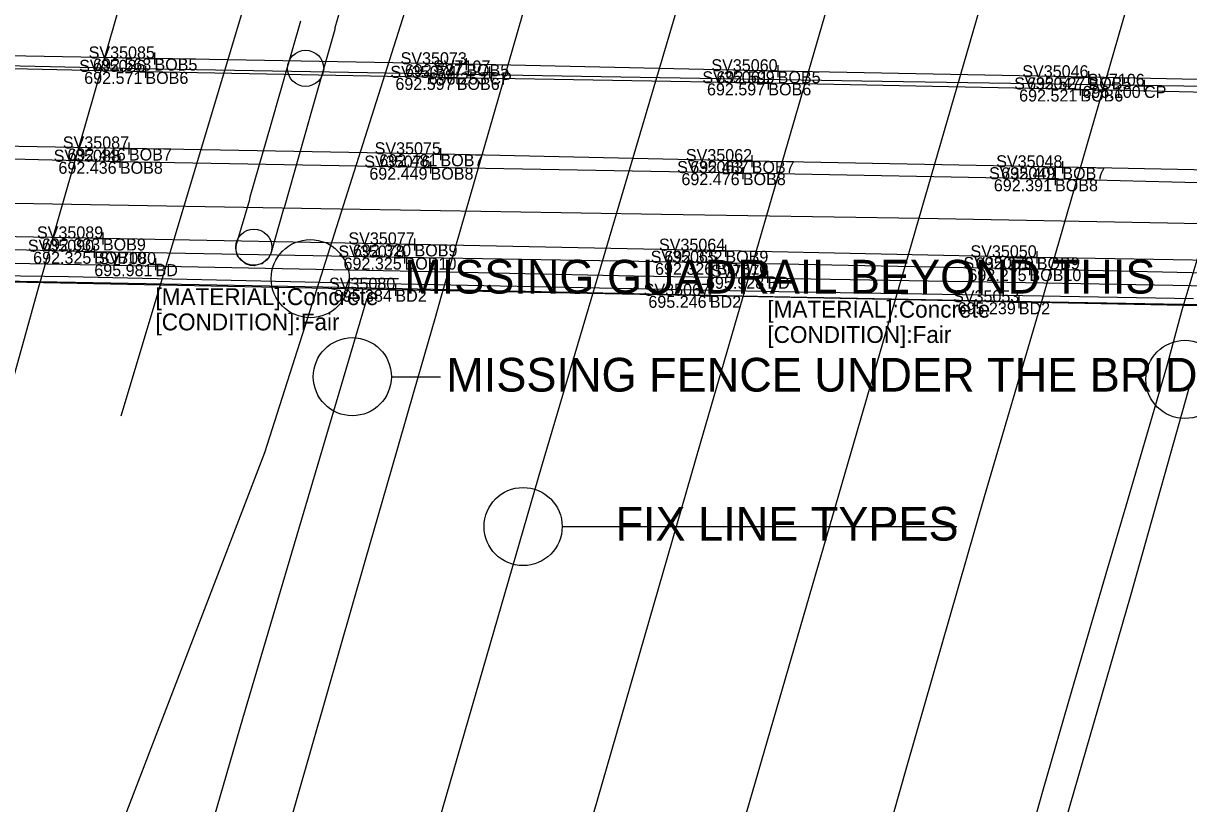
# Model space of a CAD drawing. Extents: x 1659932 to 1663108, y 619867 to 620611.
# Drawn here: x 1661352.9 to 1661449.7, y 620170.2 to 620235.1 of the extents above; entities that cross this region are included whole.
import ezdxf

# ---------------------------------------------------------------- set-up
doc = ezdxf.new("R2010")
doc.units = 0
for name, color, linetype in [('BR_X_Rail_Object', 7, 'Continuous'), ('BR_X_SV_Bottom_of_Beam', 7, 'Continuous'), ('BR_X_SV_Bottom_of_Beam_Text', 7, 'Continuous'), ('BR_X_SV_Deck_Top', 7, 'Continuous'), ('BR_X_SV_Deck_Top_Text', 7, 'Continuous'), ('BR_X_SV_Pier_Cap_Top', 7, 'Continuous'), ('PM_X_CL_Double_Solid', 7, 'Continuous'), ('PM_X_Edge_Line', 7, 'Continuous'), ('PM_X_Lane_Line', 7, 'Continuous'), ('PV_X_EOP', 7, 'Continuous'), ('RD_X_Fence', 7, 'Continuous'), ('RD_X_GR_Lt', 7, 'Continuous'), ('RD_X_GR_Rt', 7, 'Continuous'), ('SC_Scratch6', 7, 'Continuous'), ('SV_X_Break_Lines', 7, 'Continuous'), ('SV_X_Shot_Marker', 7, 'Continuous'), ('SV_X_Text', 7, 'Continuous'), ('SV_X_Text_Comment', 7, 'Continuous'), ('SV_X_Text_Elevation', 7, 'Continuous'), ('SV_X_Text_Name', 7, 'Continuous')]:
    doc.layers.add(name, color=color, linetype=linetype)

msp = doc.modelspace()

# ---------------------------------------------------------------- linework, layer by layer
at = {"layer": 'BR_X_Rail_Object'}
for points in [[(1661277.086, 620215.156), (1661299.829, 620214.642), (1661320.762, 620214.229), (1661340.158, 620213.856), (1661357.268, 620213.542), (1661379.28, 620213.128), (1661397.221, 620212.742), (1661415.211, 620212.369), (1661433.513, 620212.015), (1661450.818, 620211.691)], [(1661450.154, 620212.164), (1661434.35, 620212.457), (1661415.687, 620212.757), (1661398.089, 620213.11), (1661378.816, 620213.501), (1661356.678, 620213.984), (1661338.689, 620214.253), (1661319.507, 620214.681), (1661300.196, 620215.004), (1661277.496, 620215.529)]]:
    msp.add_lwpolyline(points, dxfattribs=at)
at = {"layer": 'BR_X_SV_Bottom_of_Beam'}
for points in [[(1661519.081, 620228.953), (1661493.234, 620229.438), (1661467.368, 620230.031), (1661441.422, 620230.57), (1661415.6, 620231.071), (1661389.731, 620231.651), (1661363.823, 620232.132), (1661337.817, 620232.613), (1661311.988, 620233.076), (1661286.183, 620233.721), (1661260.328, 620234.129), (1661234.382, 620234.656)], [(1661518.51, 620227.977), (1661492.527, 620228.475), (1661466.56, 620228.954), (1661440.742, 620229.56), (1661414.823, 620230.069), (1661388.938, 620230.522), (1661363.07, 620231.021), (1661337.298, 620231.612), (1661311.527, 620232.162), (1661285.446, 620232.587), (1661259.588, 620233.138), (1661233.669, 620233.674)], [(1661516.938, 620221.488), (1661491.079, 620222.019), (1661465.187, 620222.58), (1661439.251, 620223.092), (1661413.441, 620223.61), (1661387.584, 620224.174), (1661361.703, 620224.657), (1661335.742, 620225.126), (1661309.876, 620225.693), (1661284.015, 620226.238), (1661258.155, 620226.696), (1661232.1, 620227.235)], [(1661516.255, 620220.542), (1661490.624, 620220.907), (1661464.53, 620221.454), (1661438.64, 620222.101), (1661412.707, 620222.613), (1661386.76, 620223.066), (1661360.949, 620223.557), (1661335.05, 620224.176), (1661309.206, 620224.717), (1661283.267, 620225.126), (1661257.537, 620225.694), (1661231.605, 620226.262)], [(1661514.756, 620214.059), (1661488.914, 620214.555), (1661463.017, 620215.148), (1661437.126, 620215.616), (1661411.256, 620216.167), (1661385.428, 620216.691), (1661359.541, 620217.184), (1661333.602, 620217.682), (1661307.754, 620218.183), (1661281.891, 620218.773), (1661255.858, 620219.275), (1661229.67, 620219.799)], [(1661514.073, 620213.08), (1661488.21, 620213.597), (1661462.263, 620214.044), (1661436.515, 620214.643), (1661410.516, 620215.165), (1661384.602, 620215.601), (1661358.815, 620216.084), (1661332.968, 620216.701), (1661307.113, 620217.251), (1661281.101, 620217.691), (1661255.319, 620218.266), (1661229.464, 620218.851)]]:
    msp.add_lwpolyline(points, dxfattribs=at)
at = {"layer": 'BR_X_SV_Deck_Top'}
msp.add_lwpolyline([(1661513.529, 620210.295), (1661487.664, 620211.099), (1661461.66, 620211.354), (1661435.632, 620211.885), (1661409.962, 620212.424), (1661383.838, 620212.928), (1661332.298, 620213.947), (1661306.248, 620214.439), (1661280.429, 620214.969), (1661254.732, 620215.771)], dxfattribs=at)
at = {"layer": 'BR_X_SV_Pier_Cap_Top'}
msp.add_lwpolyline([(1661380.938, 620242.011), (1661378.818, 620234.677), (1661378.805, 620234.545), (1661376.714, 620227.175), (1661376.664, 620227.078), (1661374.594, 620219.738), (1661374.533, 620219.633), (1661373.508, 620216.005), (1661373.304, 620215.554), (1661373.028, 620215.339), (1661372.782, 620215.083), (1661372.463, 620215.014), (1661372.113, 620214.903), (1661371.815, 620214.94), (1661371.397, 620215.075), (1661371.042, 620215.405), (1661370.729, 620215.71), (1661370.615, 620216.195), (1661370.607, 620216.504), (1661370.678, 620216.801), (1661371.744, 620220.429), (1661371.783, 620220.63), (1661373.87, 620227.928), (1661373.92, 620228.026), (1661375.992, 620235.256)], dxfattribs=at)
at = {"layer": 'PM_X_CL_Double_Solid'}
msp.add_lwpolyline([(1661546.991, 620228.003), (1661534.02, 620228.314), (1661515.703, 620228.672), (1661490.63, 620229.199), (1661465.719, 620229.574), (1661443.889, 620229.917), (1661424.27, 620230.219), (1661405.796, 620230.53), (1661384.669, 620230.881), (1661362.569, 620231.272), (1661341.508, 620231.739), (1661317.992, 620232.235), (1661293.686, 620232.891), (1661270.168, 620233.351), (1661246.396, 620233.829), (1661221.676, 620234.257), (1661205.714, 620234.618)], dxfattribs=at)
at = {"layer": 'PM_X_Edge_Line'}
for p, q in [((1661400.11, 620212.126), (1661411.11, 620249.281)), ((1661448.095, 620248.463), (1661437.387, 620211.448))]:
    msp.add_line(p, q, dxfattribs=at)
for points in [[(1661202.201, 620223.591), (1661213.111, 620223.268), (1661228.394, 620222.766), (1661259.553, 620221.998), (1661275.152, 620221.639), (1661292.516, 620221.273), (1661314.563, 620220.783), (1661337.968, 620220.356), (1661364.828, 620219.904), (1661379.245, 620219.635), (1661405.952, 620219.205), (1661427.476, 620218.875), (1661447.989, 620218.475), (1661471.403, 620218.024), (1661496.022, 620217.585), (1661519.238, 620217.199), (1661540.284, 620216.766), (1661543.975, 620216.723)], [(1661306.71, 619886.778), (1661316.268, 619920.92), (1661327.099, 619959.195), (1661339.626, 620003.423), (1661350.518, 620041.544), (1661361.573, 620079.456), (1661372.715, 620118.483), (1661384.459, 620158.407), (1661395.985, 620198.192), (1661400.11, 620212.126)], [(1661437.387, 620211.448), (1661432.744, 620195.727), (1661426.311, 620173.263), (1661420.721, 620153.567), (1661415.987, 620137.071), (1661411.465, 620121.721), (1661406.956, 620105.485), (1661401.842, 620087.622), (1661396.469, 620069.251), (1661391.034, 620050.3), (1661384.749, 620028.544), (1661378.434, 620007.007), (1661371.358, 619982.439), (1661363.477, 619954.98), (1661355.622, 619926.778), (1661348.804, 619903.188), (1661342.453, 619880.74)]]:
    msp.add_lwpolyline(points, dxfattribs=at)
at = {"layer": 'PM_X_Lane_Line'}
for p, q in [((1661409.184, 620200.168), (1661424.053, 620251.255)), ((1661436.528, 620250.631), (1661421.891, 620200.155))]:
    msp.add_line(p, q, dxfattribs=at)
for points in [[(1661320.334, 619891.193), (1661330.953, 619928.285), (1661342.834, 619969.596), (1661354.182, 620009.137), (1661364.936, 620046.768), (1661375.793, 620084.601), (1661387.194, 620123.919), (1661398.334, 620162.593), (1661409.184, 620200.168)], [(1661421.891, 620200.155), (1661410.557, 620161.046), (1661398.591, 620119.699), (1661388.314, 620083.982), (1661377.532, 620046.533), (1661365.852, 620005.722), (1661355.434, 619969.431), (1661344.025, 619929.62), (1661333.166, 619890.94)]]:
    msp.add_lwpolyline(points, dxfattribs=at)
at = {"layer": 'PV_X_EOP'}
for p, q in [((1661364.882, 620250.347), (1661354.068, 620212.758)), ((1661387.682, 620212.413), (1661398.34, 620249.454)), ((1661460.209, 620248.191), (1661449.175, 620211.228))]:
    msp.add_line(p, q, dxfattribs=at)
for points in [[(1661354.068, 620212.758), (1661351.456, 620203.266), (1661348.504, 620193.032), (1661343.865, 620176.722), (1661338.343, 620157.33), (1661329.496, 620126.951), (1661323.428, 620105.423), (1661317.627, 620085.661), (1661309.752, 620058.017), (1661302.017, 620030.687), (1661292.653, 619998.313), (1661288.526, 619983.086), (1661284.456, 619969.782), (1661279.629, 619952.971), (1661274.634, 619935.67), (1661263.801, 619897.546), (1661258.099, 619878.266)], [(1661288.662, 619867.177), (1661292.293, 619880.139), (1661297.982, 619900.237), (1661302.563, 619916.13), (1661307.386, 619933.253), (1661312.432, 619950.929), (1661316.287, 619964.745), (1661318.419, 619972.097), (1661332.213, 620019.935), (1661339.457, 620045.301), (1661345.341, 620066.158), (1661348.977, 620078.854), (1661352.806, 620092.257), (1661356.714, 620105.692), (1661360.704, 620119.003), (1661364.644, 620132.564), (1661371.894, 620157.469), (1661378.106, 620179.182), (1661381.364, 620190.492), (1661383.517, 620197.974), (1661385.373, 620204.43), (1661387.148, 620210.533), (1661387.682, 620212.413)], [(1661449.175, 620211.228), (1661447.901, 620206.5), (1661444.533, 620194.957), (1661443.009, 620189.805), (1661440.022, 620179.591), (1661437.667, 620171.441), (1661433.645, 620157.193), (1661427.975, 620137.724), (1661425.116, 620127.734), (1661422.329, 620118.155), (1661418.054, 620103.53), (1661414.465, 620091.14), (1661411.007, 620079.046), (1661408.706, 620071.095), (1661405.629, 620060.218), (1661402.596, 620050.021), (1661399.373, 620038.801), (1661396.017, 620026.958)]]:
    msp.add_lwpolyline(points, dxfattribs=at)
at = {"layer": 'RD_X_Fence'}
msp.add_lwpolyline([(1661324.855, 620042.073), (1661333.159, 620048.256), (1661338.09, 620064.232), (1661346.292, 620092.377), (1661351.34, 620109.776), (1661359.715, 620137.883), (1661371.17, 620177.306), (1661381.505, 620212.212)], dxfattribs=at)
at = {"layer": 'RD_X_GR_Lt'}
for p, q in [((1661376.955, 620211.812), (1661392.542, 620260.947)), ((1661377.013, 620255.729), (1661361.042, 620202.435))]:
    msp.add_line(p, q, dxfattribs=at)
msp.add_lwpolyline([(1661337.672, 620097.681), (1661344.162, 620121.221), (1661348.962, 620136.596), (1661353.107, 620148.16), (1661357.657, 620159.513), (1661368.944, 620188.88), (1661372.986, 620199.407), (1661376.955, 620211.812)], dxfattribs=at)
at = {"layer": 'RD_X_GR_Rt'}
msp.add_lwpolyline([(1661385.522, 619982.005), (1661394.011, 620012.081), (1661399.542, 620030.546), (1661408.076, 620060.366), (1661416.511, 620089.472), (1661427.104, 620125.794), (1661434.884, 620152.781), (1661444.901, 620187.452), (1661449.997, 620205.546)], dxfattribs=at)
at = {"layer": 'SC_Scratch6'}
for p, q in [((1661380.008, 620213.845), (1661384.099, 620213.845)), ((1661383.507, 620205.702), (1661387.597, 620205.702)), ((1661397.694, 620193.255), (1661430.498, 620193.255))]:
    msp.add_line(p, q, dxfattribs=at)
for centre in [(1661376.763, 620213.845), (1661380.262, 620205.702), (1661449.432, 620205.478), (1661394.45, 620193.255)]:
    msp.add_circle(centre, 3.245, dxfattribs=at)
at = {"layer": 'SV_X_Break_Lines'}
msp.add_lwpolyline([(1661228.67, 620217.714), (1661237.329, 620217.546), (1661248.531, 620217.329), (1661262.126, 620217.116), (1661283.4, 620216.641), (1661303.8, 620216.137), (1661335.243, 620215.455), (1661384.24, 620214.497), (1661403.674, 620214.086), (1661434.655, 620213.563), (1661466.755, 620212.973), (1661495.661, 620212.446), (1661513.396, 620212.012)], dxfattribs=at)
for centre in [(1661376.383, 620231.314), (1661372.074, 620216.454)]:
    msp.add_circle(centre, 1.5, dxfattribs=at)
at = {"layer": 'SV_X_Shot_Marker'}
for p, q in [((1661363.823, 620232.632), (1661363.823, 620231.632)), ((1661363.07, 620231.521), (1661363.07, 620230.521)), ((1661363.323, 620232.132), (1661364.323, 620232.132)), ((1661363.823, 620232.132), (1661363.823, 620232.132)), ((1661389.231, 620231.651), (1661390.231, 620231.651)), ((1661389.731, 620232.151), (1661389.731, 620231.151)), ((1661389.731, 620231.651), (1661389.731, 620231.651)), ((1661391.661, 620231.469), (1661391.661, 620230.469)), ((1661415.6, 620231.571), (1661415.6, 620230.571)), ((1661362.57, 620231.021), (1661363.57, 620231.021)), ((1661363.07, 620231.021), (1661363.07, 620231.021)), ((1661388.438, 620230.522), (1661389.438, 620230.522)), ((1661388.938, 620231.022), (1661388.938, 620230.022)), ((1661388.938, 620230.522), (1661388.938, 620230.522)), ((1661391.161, 620230.969), (1661392.161, 620230.969)), ((1661391.661, 620230.969), (1661391.661, 620230.969)), ((1661414.823, 620230.569), (1661414.823, 620229.569)), ((1661415.1, 620231.071), (1661416.1, 620231.071)), ((1661415.6, 620231.071), (1661415.6, 620231.071)), ((1661440.922, 620230.57), (1661441.922, 620230.57)), ((1661441.422, 620231.07), (1661441.422, 620230.07)), ((1661441.422, 620230.57), (1661441.422, 620230.57)), ((1661446.036, 620230.358), (1661446.036, 620229.358)), ((1661414.323, 620230.069), (1661415.323, 620230.069)), ((1661414.823, 620230.069), (1661414.823, 620230.069)), ((1661440.242, 620229.56), (1661441.242, 620229.56)), ((1661440.742, 620230.06), (1661440.742, 620229.06)), ((1661440.742, 620229.56), (1661440.742, 620229.56)), ((1661445.536, 620229.858), (1661446.536, 620229.858)), ((1661446.036, 620229.858), (1661446.036, 620229.858)), ((1661361.203, 620224.657), (1661362.203, 620224.657)), ((1661361.703, 620225.157), (1661361.703, 620224.157)), ((1661361.703, 620224.657), (1661361.703, 620224.657)), ((1661387.584, 620224.674), (1661387.584, 620223.674)), ((1661360.449, 620223.557), (1661361.449, 620223.557)), ((1661360.949, 620224.057), (1661360.949, 620223.057)), ((1661360.949, 620223.557), (1661360.949, 620223.557)), ((1661386.76, 620223.566), (1661386.76, 620222.566)), ((1661387.084, 620224.174), (1661388.084, 620224.174)), ((1661387.584, 620224.174), (1661387.584, 620224.174)), ((1661412.941, 620223.61), (1661413.941, 620223.61)), ((1661413.441, 620224.11), (1661413.441, 620223.11)), ((1661413.441, 620223.61), (1661413.441, 620223.61)), ((1661439.251, 620223.592), (1661439.251, 620222.592)), ((1661386.26, 620223.066), (1661387.26, 620223.066)), ((1661386.76, 620223.066), (1661386.76, 620223.066)), ((1661412.207, 620222.613), (1661413.207, 620222.613)), ((1661412.707, 620223.113), (1661412.707, 620222.113)), ((1661412.707, 620222.613), (1661412.707, 620222.613)), ((1661438.64, 620222.601), (1661438.64, 620221.601)), ((1661438.751, 620223.092), (1661439.751, 620223.092)), ((1661439.251, 620223.092), (1661439.251, 620223.092)), ((1661438.14, 620222.101), (1661439.14, 620222.101)), ((1661438.64, 620222.101), (1661438.64, 620222.101)), ((1661359.541, 620217.684), (1661359.541, 620216.684)), ((1661359.041, 620217.184), (1661360.041, 620217.184)), ((1661359.541, 620217.184), (1661359.541, 620217.184)), ((1661384.928, 620216.691), (1661385.928, 620216.691)), ((1661385.428, 620217.191), (1661385.428, 620216.191)), ((1661385.428, 620216.691), (1661385.428, 620216.691)), ((1661358.315, 620216.084), (1661359.315, 620216.084)), ((1661358.815, 620216.584), (1661358.815, 620215.584)), ((1661358.815, 620216.084), (1661358.815, 620216.084)), ((1661384.602, 620216.101), (1661384.602, 620215.101)), ((1661410.756, 620216.167), (1661411.756, 620216.167)), ((1661411.256, 620216.667), (1661411.256, 620215.667)), ((1661411.256, 620216.167), (1661411.256, 620216.167)), ((1661437.126, 620216.116), (1661437.126, 620215.116)), ((1661363.408, 620215.05), (1661364.408, 620215.05)), ((1661363.908, 620215.55), (1661363.908, 620214.55)), ((1661363.908, 620215.05), (1661363.908, 620215.05)), ((1661384.102, 620215.601), (1661385.102, 620215.601)), ((1661384.602, 620215.601), (1661384.602, 620215.601)), ((1661410.016, 620215.165), (1661411.016, 620215.165)), ((1661410.516, 620215.665), (1661410.516, 620214.665)), ((1661410.516, 620215.165), (1661410.516, 620215.165)), ((1661436.515, 620215.143), (1661436.515, 620214.143)), ((1661436.626, 620215.616), (1661437.626, 620215.616)), ((1661437.126, 620215.616), (1661437.126, 620215.616)), ((1661414.245, 620214.006), (1661415.245, 620214.006)), ((1661414.745, 620214.506), (1661414.745, 620213.506)), ((1661414.745, 620214.006), (1661414.745, 620214.006)), ((1661436.015, 620214.643), (1661437.015, 620214.643)), ((1661436.515, 620214.643), (1661436.515, 620214.643)), ((1661383.338, 620212.928), (1661384.338, 620212.928)), ((1661383.838, 620213.428), (1661383.838, 620212.428)), ((1661383.838, 620212.928), (1661383.838, 620212.928)), ((1661409.962, 620212.924), (1661409.962, 620211.924)), ((1661409.462, 620212.424), (1661410.462, 620212.424)), ((1661409.962, 620212.424), (1661409.962, 620212.424)), ((1661435.132, 620211.885), (1661436.132, 620211.885)), ((1661435.632, 620212.385), (1661435.632, 620211.385)), ((1661435.632, 620211.885), (1661435.632, 620211.885))]:
    msp.add_line(p, q, dxfattribs=at)

# ---------------------------------------------------------------- texts
at = {"layer": 'BR_X_SV_Bottom_of_Beam_Text'}
for s, p in [('SV35085', (1661358.356, 620232.132)), ('SV35073', (1661384.271, 620231.651)), ('SV35086', (1661357.57, 620231.021)), ('692.568', (1661358.723, 620231.132)), ('BOB5', (1661363.823, 620231.132)), ('SV35074', (1661383.42, 620230.522)), ('692.587', (1661384.635, 620230.651)), ('BOB5', (1661389.731, 620230.651)), ('SV35060', (1661410.09, 620231.071)), ('SV35046', (1661435.922, 620230.57)), ('692.571', (1661357.988, 620230.021)), ('BOB6', (1661363.07, 620230.021)), ('692.597', (1661383.842, 620229.522)), ('BOB6', (1661388.938, 620229.522)), ('SV35061', (1661409.345, 620230.069)), ('692.599', (1661410.516, 620230.071)), ('BOB5', (1661415.6, 620230.071)), ('SV35047', (1661435.25, 620229.56)), ('692.527', (1661436.326, 620229.57)), ('BOB5', (1661441.422, 620229.57)), ('692.597', (1661409.727, 620229.069)), ('BOB6', (1661414.823, 620229.069)), ('692.521', (1661435.66, 620228.56)), ('BOB6', (1661440.742, 620228.56)), ('SV35087', (1661356.211, 620224.657)), ('SV35088', (1661355.452, 620223.557)), ('692.446', (1661356.599, 620223.657)), ('BOB7', (1661361.703, 620223.657)), ('SV35075', (1661382.117, 620224.174)), ('SV35062', (1661407.972, 620223.61)), ('692.436', (1661355.845, 620222.557)), ('BOB8', (1661360.949, 620222.557)), ('SV35076', (1661381.26, 620223.066)), ('692.481', (1661382.502, 620223.174)), ('BOB7', (1661387.584, 620223.174)), ('SV35063', (1661407.247, 620222.613)), ('692.487', (1661408.345, 620222.61)), ('BOB7', (1661413.441, 620222.61)), ('SV35048', (1661433.754, 620223.092)), ('692.449', (1661381.676, 620222.066)), ('BOB8', (1661386.76, 620222.066)), ('692.476', (1661407.603, 620221.613)), ('BOB8', (1661412.707, 620221.613)), ('SV35049', (1661433.16, 620222.101)), ('692.401', (1661434.169, 620222.092)), ('BOB7', (1661439.251, 620222.092)), ('692.391', (1661433.558, 620221.101)), ('BOB8', (1661438.64, 620221.101)), ('SV35089', (1661354.061, 620217.184)), ('SV35077', (1661379.936, 620216.691)), ('SV35090', (1661353.305, 620216.084)), ('692.333', (1661354.477, 620216.184)), ('BOB9', (1661359.541, 620216.184)), ('692.320', (1661380.314, 620215.691)), ('BOB9', (1661385.428, 620215.691)), ('SV35064', (1661405.738, 620216.167)), ('692.325', (1661353.745, 620215.084)), ('BOB10', (1661358.815, 620215.084)), ('SV35078', (1661379.105, 620215.601)), ('SV35065', (1661405.049, 620215.165)), ('692.332', (1661406.183, 620215.167)), ('BOB9', (1661411.256, 620215.167)), ('SV35050', (1661431.616, 620215.616)), ('692.325', (1661379.532, 620214.601)), ('BOB10', (1661384.602, 620214.601)), ('692.326', (1661405.412, 620214.165)), ('BOB10', (1661410.516, 620214.165)), ('SV35051', (1661431.037, 620214.643)), ('692.279', (1661432.042, 620214.616)), ('BOB9', (1661437.126, 620214.616)), ('692.275', (1661431.445, 620213.643)), ('BOB10', (1661436.515, 620213.643))]:
    msp.add_text(s, height=1, dxfattribs=at).set_placement(p)
at = {"layer": 'BR_X_SV_Deck_Top_Text'}
for s, p in [('SV7080', (1661359.196, 620215.05)), ('695.981', (1661358.826, 620214.05)), ('BD', (1661363.908, 620214.05)), ('SV7079', (1661410.063, 620214.006)), ('SV35080', (1661378.328, 620212.928)), ('695.928', (1661409.645, 620213.006)), ('BD', (1661414.745, 620213.006)), ('695.384', (1661378.716, 620211.928)), ('BD2', (1661383.838, 620211.928)), ('SV35067', (1661404.47, 620212.424)), ('SV35053', (1661430.172, 620211.885)), ('695.246', (1661404.858, 620211.424)), ('BD2', (1661409.962, 620211.424)), ('695.239', (1661430.548, 620210.885)), ('BD2', (1661435.632, 620210.885))]:
    msp.add_text(s, height=1, dxfattribs=at).set_placement(p)
at = {"layer": 'SC_Scratch6'}
for s, p in [('MISSING GUADRAIL BEYOND THIS', (1661384.567, 620212.609)), ('MISSING FENCE UNDER THE BRIDGE', (1661388.066, 620204.466)), ('FIX LINE TYPES', (1661402.124, 620192.089))]:
    msp.add_text(s, height=2.79999, dxfattribs=at).set_placement(p)
at = {"layer": 'SV_X_Text'}
for s, p in [('[MATERIAL]:Concrete', (1661363.908, 620211.65)), ('[MATERIAL]:Concrete', (1661414.745, 620210.606)), ('[CONDITION]:Fair', (1661363.908, 620209.55)), ('[CONDITION]:Fair', (1661414.745, 620208.506))]:
    msp.add_text(s, height=1.4, dxfattribs=at).set_placement(p)
at = {"layer": 'SV_X_Text_Comment'}
for p in [(1661391.661, 620229.969), (1661446.036, 620228.858)]:
    msp.add_text('CP', height=1, dxfattribs=at).set_placement(p)
at = {"layer": 'SV_X_Text_Elevation'}
for s, p in [('696.253', (1661386.597, 620229.969)), ('696.100', (1661440.922, 620228.858))]:
    msp.add_text(s, height=1, dxfattribs=at).set_placement(p)
at = {"layer": 'SV_X_Text_Name'}
for s, p in [('SV7107', (1661386.967, 620230.969)), ('SV7106', (1661441.334, 620229.858))]:
    msp.add_text(s, height=1, dxfattribs=at).set_placement(p)

doc.saveas('drawing.dxf')
